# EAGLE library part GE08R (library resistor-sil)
SIL RESISTOR
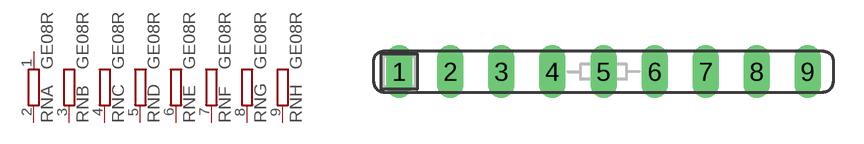
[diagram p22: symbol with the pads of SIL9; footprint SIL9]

Designator prefix RN; gates A=R-NV B=R-NV1 C=R-NV1 D=R-NV1 E=R-NV1 F=R-NV1 G=R-NV1 H=R-NV1

## GE08R (OC_FARNELL: unknown; OC_NEWARK: unknown)  [SIL9]
1  A:1  pas
2  A:2  pas
3  B:2  pas
4  C:2  pas
5  D:2  pas
6  E:2  pas
7  F:2  pas
8  G:2  pas
9  H:2  pas

## Footprint SIL9 (pad centres in mm)
Single In Line
drill 0.813 long: 1 -10.16,0; 2 -7.62,0; 3 -5.08,0; 4 -2.54,0; 5 0,0; 6 2.54,0; 7 5.08,0; 8 7.62,0; 9 10.16,0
